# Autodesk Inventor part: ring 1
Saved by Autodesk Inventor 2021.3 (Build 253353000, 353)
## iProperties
Created: 2022-02
Part Number: ring 1
Material: Generic
Document SubType Name: Modeling
Designer: Administrator
Density: 1 g/cm^3
Appearance: Default
Title: ring 1
Author: Administrator
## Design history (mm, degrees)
feature "Body1"
body "Solid1"
